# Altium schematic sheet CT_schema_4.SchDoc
size 349 x 348 mm
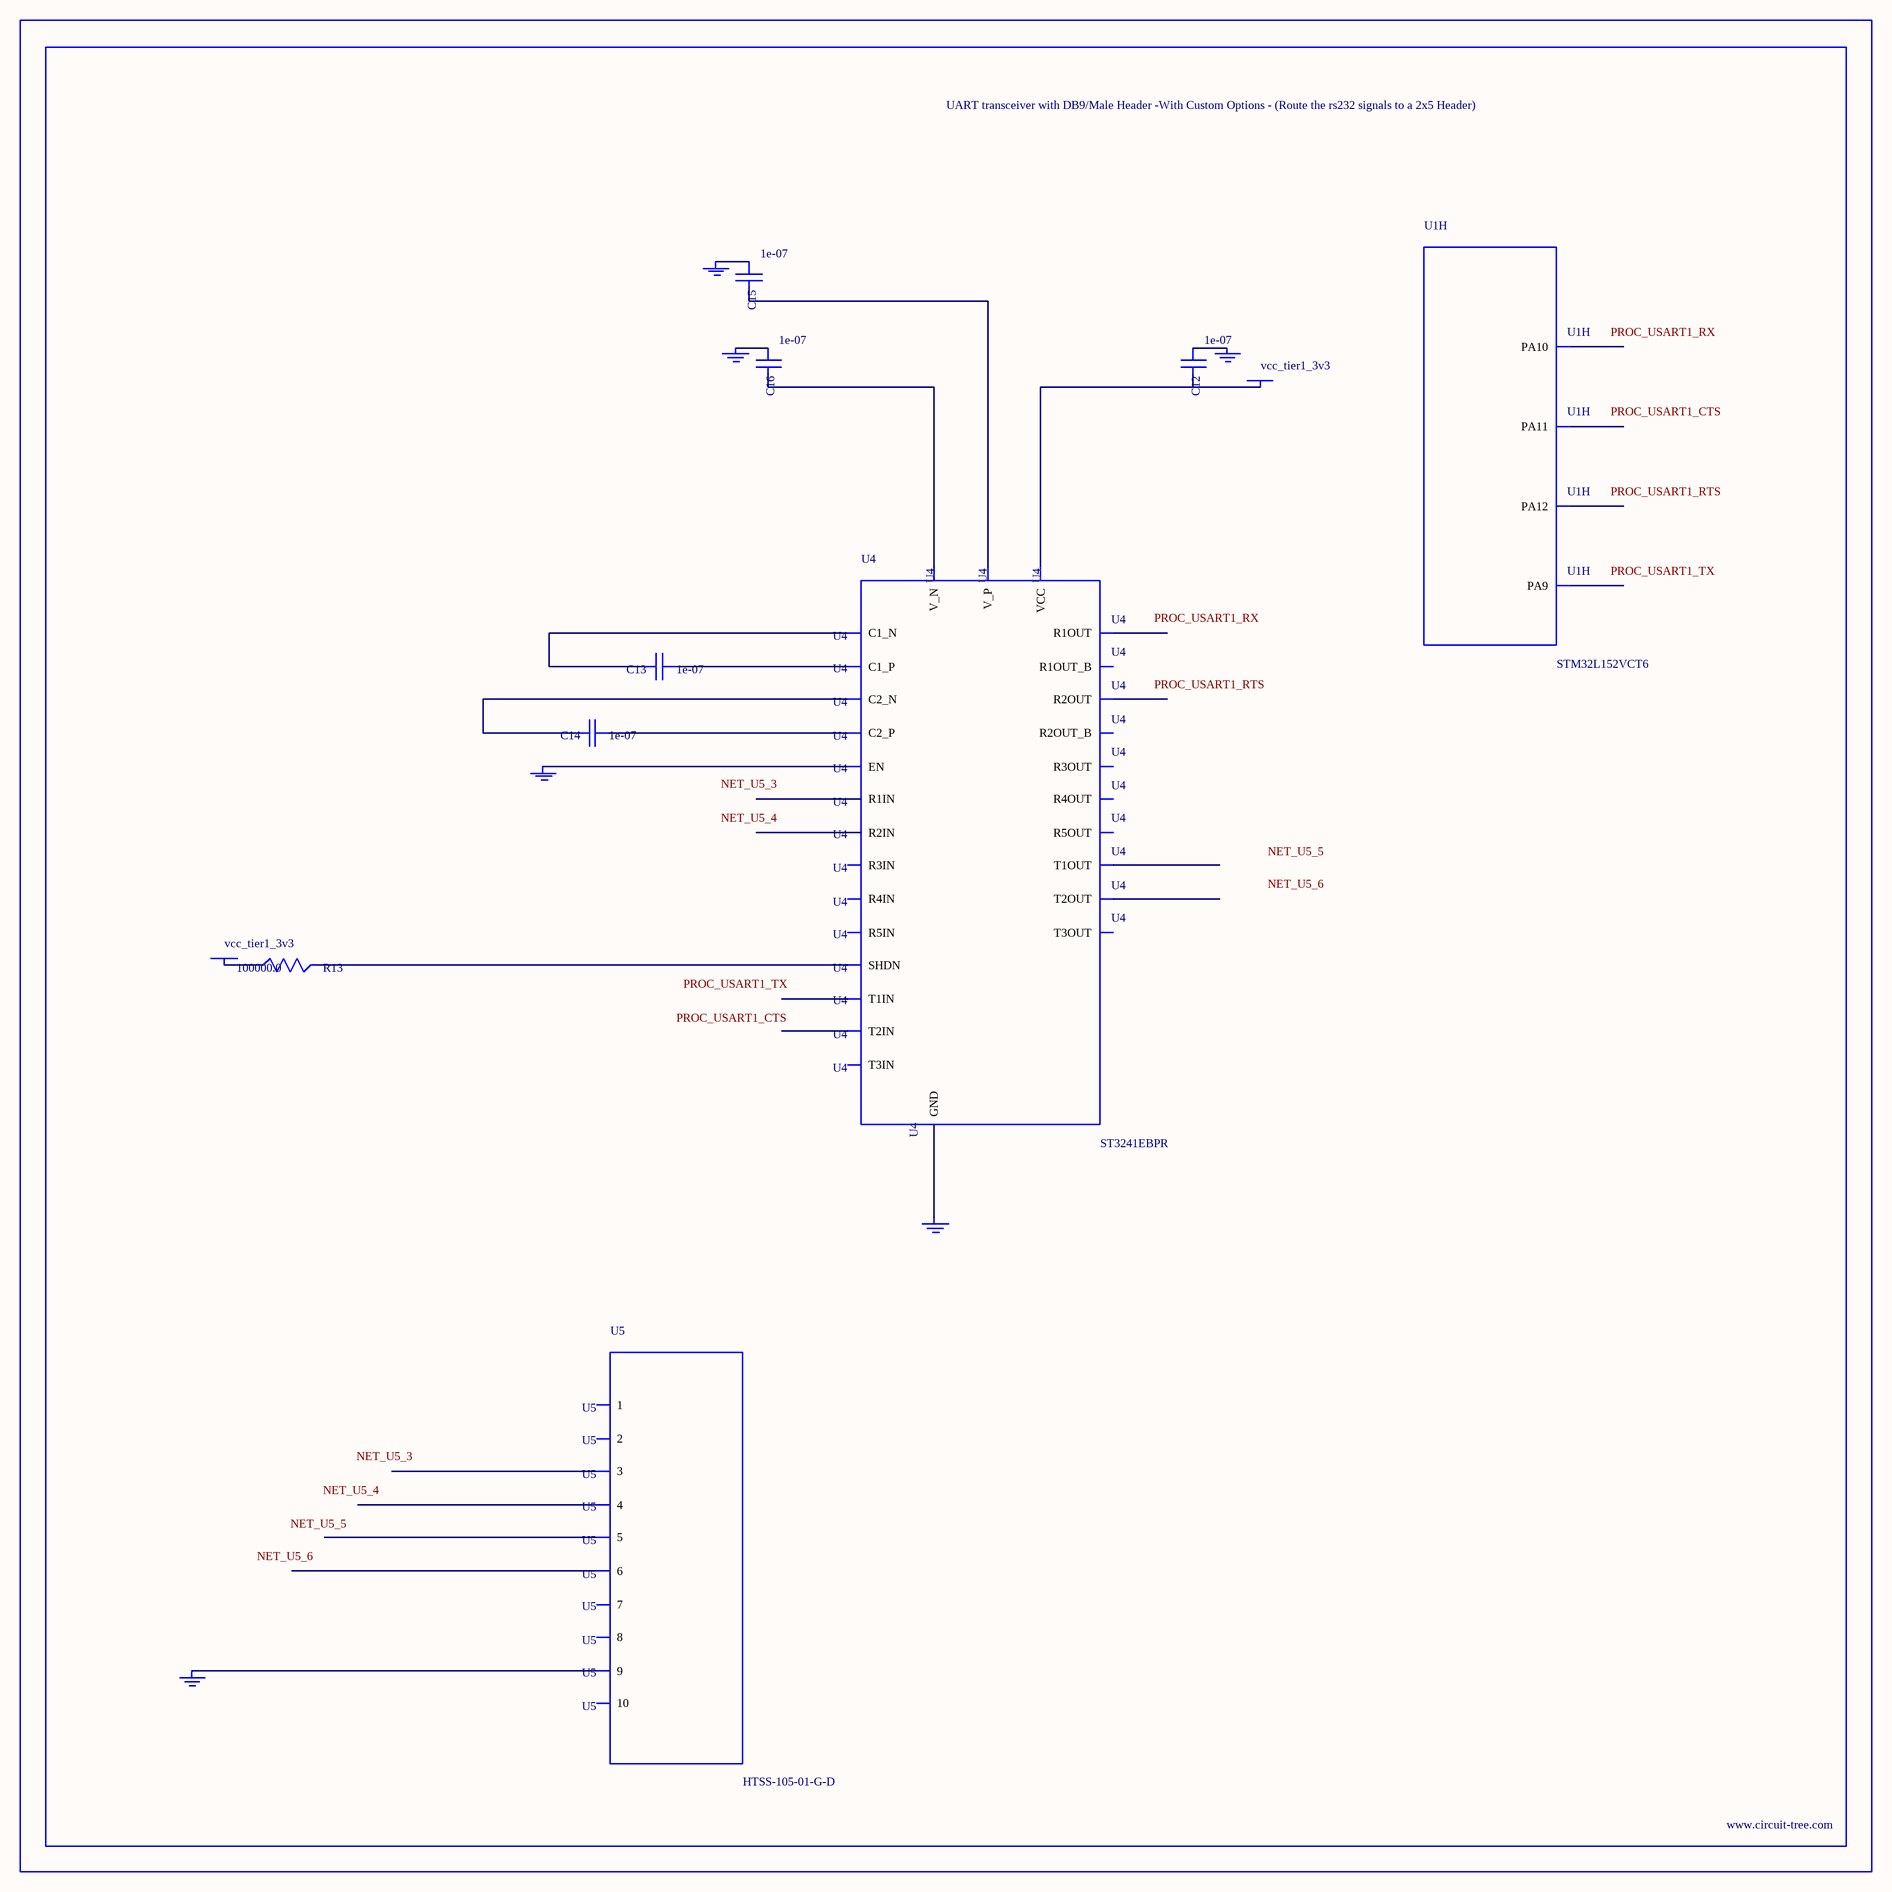
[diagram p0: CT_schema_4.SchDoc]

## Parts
BORDER3  (no value)
C12  1e-07  [C0402]
C13  1e-07  [C0402]
C14  1e-07  [C0402]
C15  1e-07  [C0402]
C16  1e-07  [C0402]
GND_INSTANCE_3_0  (no value)
GND_INSTANCE_3_1  (no value)
GND_INSTANCE_3_2  (no value)
GND_INSTANCE_3_3  (no value)
GND_INSTANCE_3_4  (no value)
GND_INSTANCE_3_5  (no value)
POWER_INSTANCE_3_0  vcc_tier1_3v3
POWER_INSTANCE_3_1  vcc_tier1_3v3
R13  100000.0  [R0603]
U1  STM32L152VCT6  [LQFP100]  (part H of 9)
U4  ST3241EBPR  [SSOP-28]
U5  HTSS-105-01-G-D  [HTSS-105-01-G-D]

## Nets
NetC12_1: C12.1 GND_INSTANCE_3_2.0(GND)
NetC12_2: C12.2 POWER_INSTANCE_3_1.0(PWR) U4.26(VCC)
NetC13_1: C13.1 U4.28(C1_P)
NetC13_2: C13.2 U4.24(C1_N)
NetC14_1: C14.1 U4.1(C2_P)
NetC14_2: C14.2 U4.2(C2_N)
NetC15_1: C15.1 GND_INSTANCE_3_3.0(GND)
NetC15_2: C15.2 U4.27(V_P)
NetC16_1: C16.1 GND_INSTANCE_3_0.0(GND)
NetC16_2: C16.2 U4.3(V_N)
NetGND_INSTANCE_3_1_0: GND_INSTANCE_3_1.0(GND) U4.23(EN)
NetGND_INSTANCE_3_4_0: GND_INSTANCE_3_4.0(GND) U4.25(GND)
NetGND_INSTANCE_3_5_0: GND_INSTANCE_3_5.0(GND) U5.9
NetPOWER_INSTANCE_3_0_0: POWER_INSTANCE_3_0.0(PWR) R13.1
NetR13_2: R13.2 U4.22(SHDN)

Not connected (* = marked no-connect by the designer): U1 68(PA9) 69(PA10) 70(PA11) 71(PA12); U4 4(R1IN) 5(R2IN) 6(R3IN) 7(R4IN) 8(R5IN) 9(T1OUT) 10(T2OUT) 11(T3OUT) 12(T3IN) 13(T2IN) 14(T1IN) 15(R5OUT) 16(R4OUT) 17(R3OUT) 18(R2OUT) 19(R1OUT) 20(R2OUT_B) 21(R1OUT_B); U5 1 2 3 4 5 6 7 8 10

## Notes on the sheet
- Labels drawn without touching a wire or pin: NET_U5_3, NET_U5_4, NET_U5_5, NET_U5_6, PROC_USART1_CTS, PROC_USART1_RTS, PROC_USART1_RX, PROC_USART1_TX

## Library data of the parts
BORDER3 = BORDER_PAGE3
C12-C16 = C0402C104K3RACTU
GND_INSTANCE_3_0-GND_INSTANCE_3_5 = GND
POWER_INSTANCE_3_0 POWER_INSTANCE_3_1 = PWR
R13 = RC0603JR-07100KL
